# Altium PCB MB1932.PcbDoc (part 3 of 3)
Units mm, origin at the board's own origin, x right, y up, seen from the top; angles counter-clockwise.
Board outline 70 x 82.5 mm, 2 copper layers (Top Layer, Bottom Layer), stack 1.543 mm thick; 185 components, 150 nets, 679 pads, 649 vias.
Unrouted connection lines stored in the file: 108.
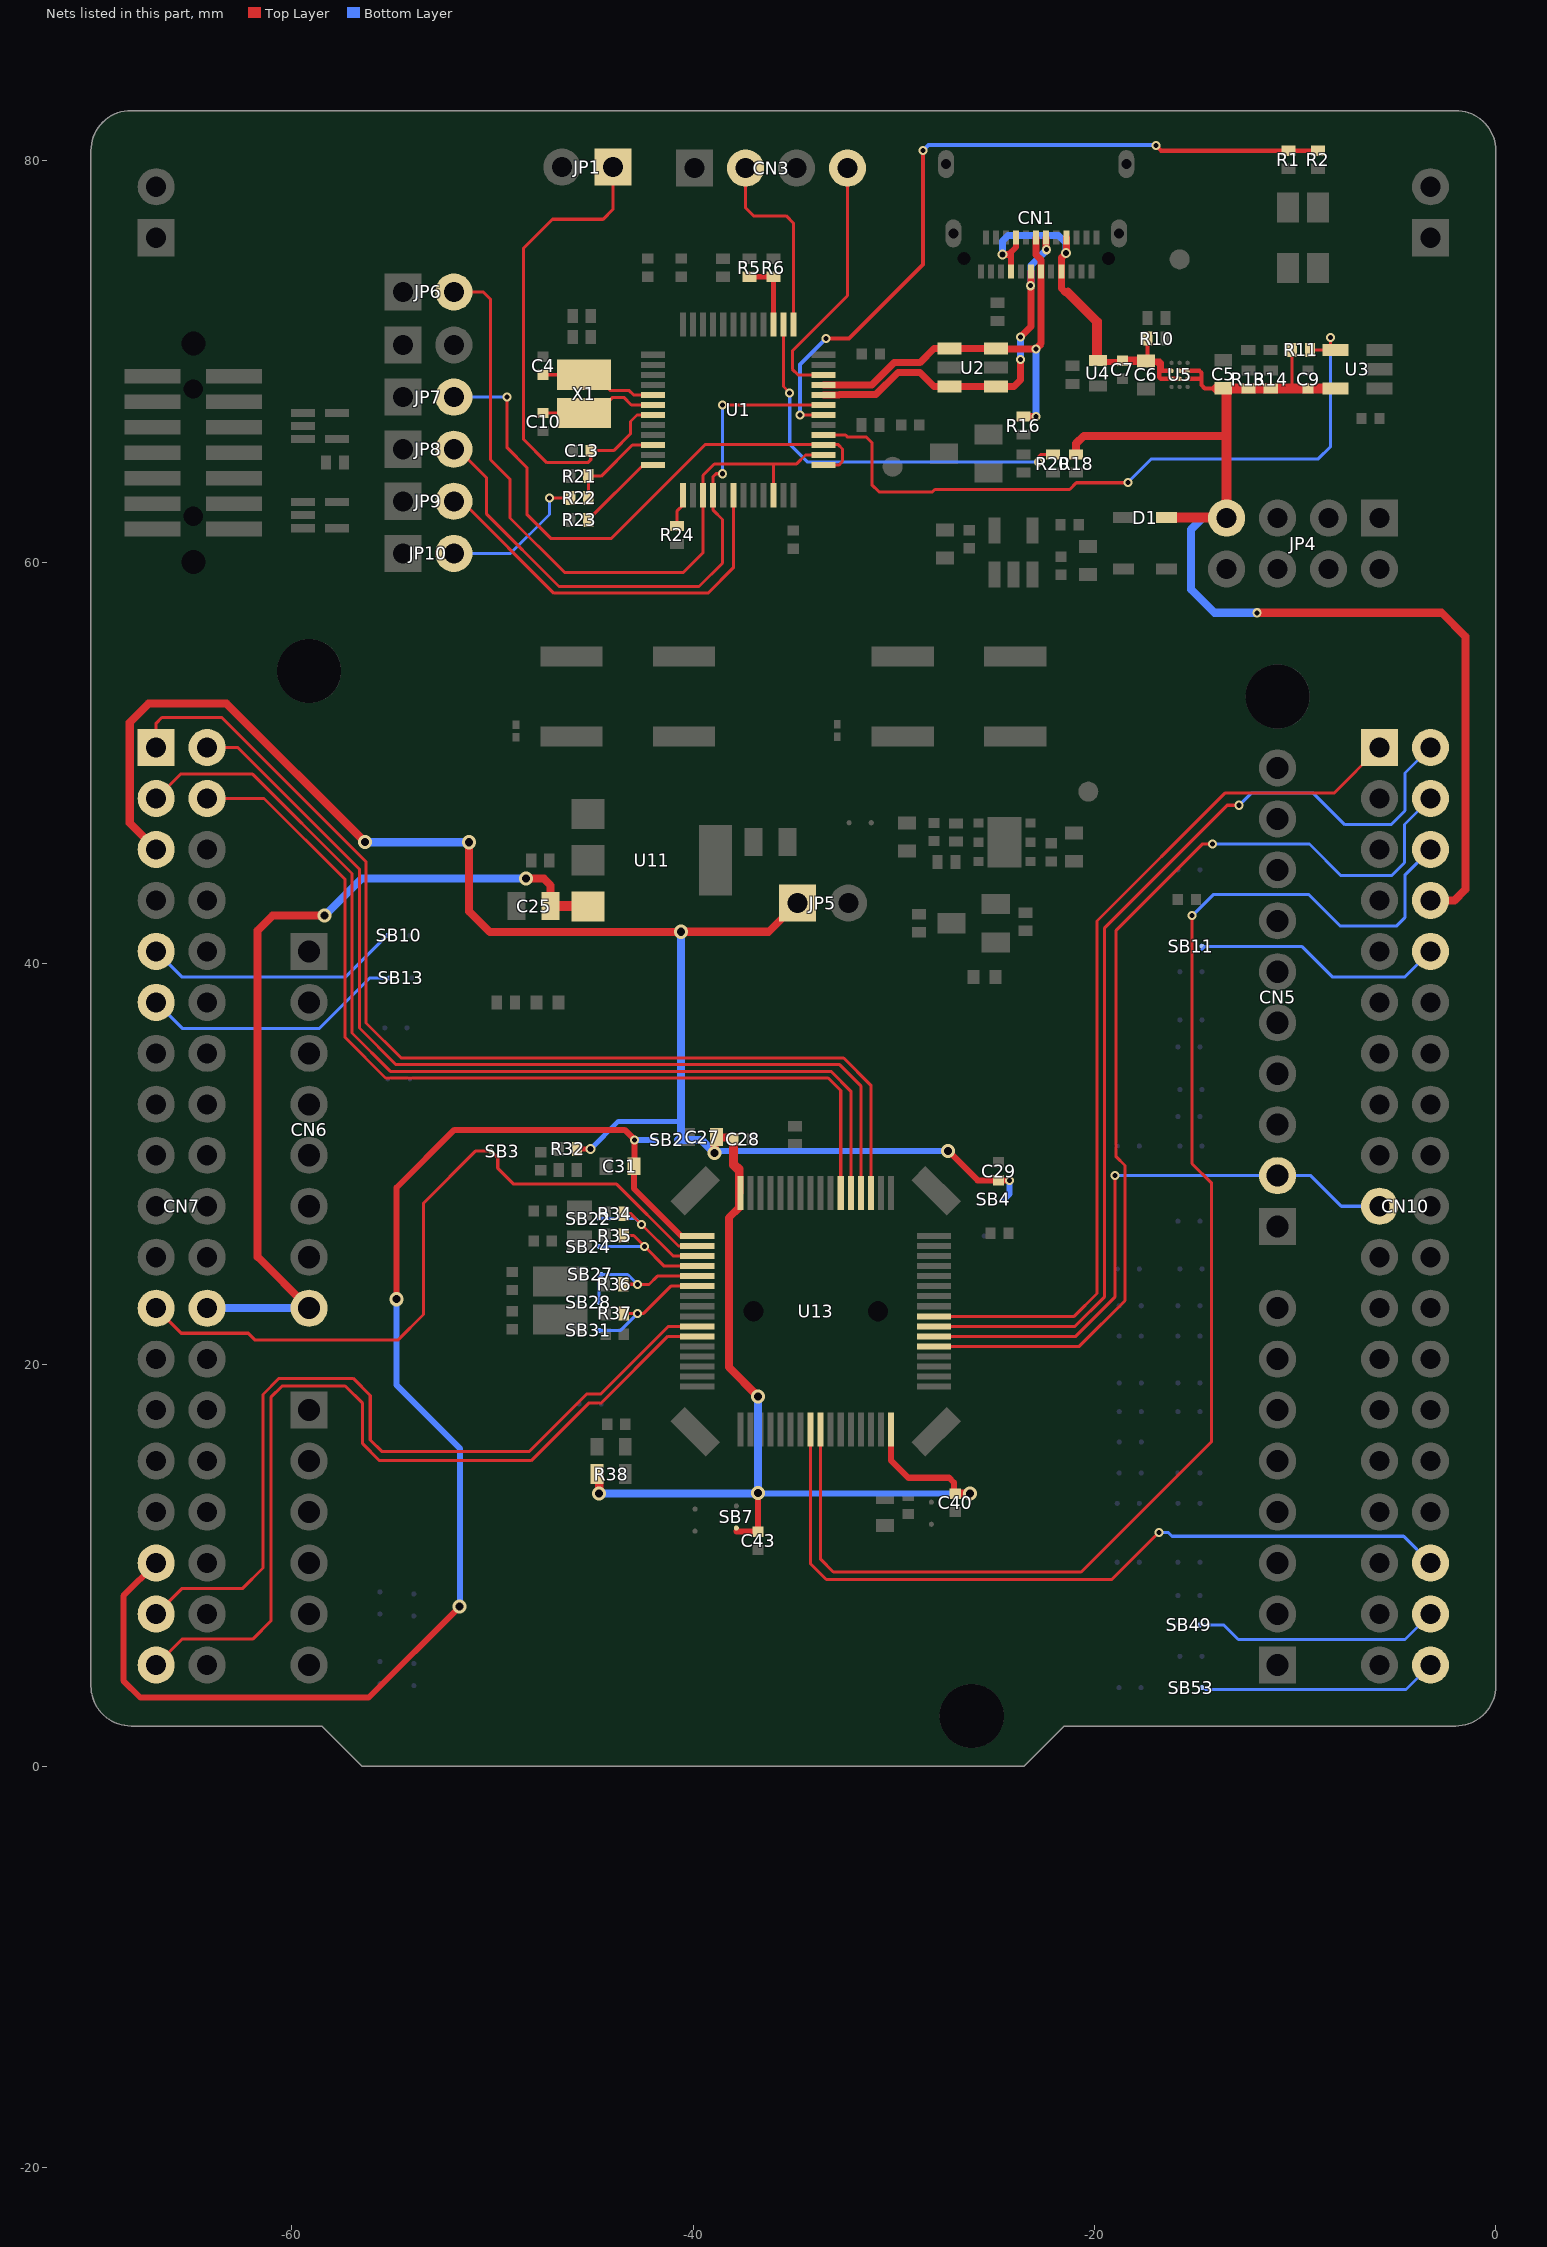
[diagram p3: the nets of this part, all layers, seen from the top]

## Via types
v1: diameter 0.45, hole 0.25, Top Layer to Bottom Layer, tented both sides, 618 vias
v2: diameter 0.7, hole 0.4, Top Layer to Bottom Layer, tented both sides, 28 vias
v3: diameter 0.5, hole 0.3, Top Layer to Bottom Layer, tented both sides, 3 vias

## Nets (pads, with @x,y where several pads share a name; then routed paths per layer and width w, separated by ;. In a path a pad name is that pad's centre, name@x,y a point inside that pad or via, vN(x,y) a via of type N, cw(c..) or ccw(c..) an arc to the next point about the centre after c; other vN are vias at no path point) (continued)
PC2: CN7.35 U13.10 | length 42.3
  Top Layer w0.152: CN7.35@-66.75,7.58 -65.483,8.847 -62.457,8.847 -61.426,9.879 -61.426,18.525 -60.626,19.325 -56.936,19.325 -56.082,18.472 -56.082,16.254 -55.513,15.685 -48.144,15.685 -45.279,18.55 -44.585,18.55 -41.218,21.918 U13.10@-39.788,21.918
PC3: CN7.37 U13.11 | length 44.5
  Top Layer w0.152: CN7.37@-66.75,5.04 -65.462,6.328 -61.942,6.328 -61.035,7.235 -61.035,18.377 -60.468,18.944 -57.33,18.944 -56.463,18.078 -56.463,16.069 -55.617,15.223 -48.067,15.223 -45.201,18.088 -44.58,18.088 -41.251,21.418 U13.11@-39.788,21.418
PC4: CN10.34 U13.24 | length 39.5
  Top Layer w0.152: U13.24@-34.138,16.768 -34.138,10.077 -33.358,9.297 -19.135,9.297 v1(-16.781,11.652)
  Bottom Layer w0.152: v1@-16.788,11.654 -16.331,11.654 -16.133,11.456 -10.371,11.456 -4.586,11.456 CN10.34@-3.25,10.12
PC5: CN10.6 U13.25 | length 71.3
  Top Layer w0.152: U13.25@-33.638,16.768 -33.638,10.307 -33.009,9.678 -20.659,9.678 -14.158,16.179 -14.158,29.052 -15.131,30.025 -15.131,42.374 v1(-15.127,42.378)
  Bottom Layer w0.152: v1(-15.127,42.378) -14.078,43.427 -9.308,43.427 -7.738,41.857 -4.957,41.857 -4.533,42.281 -4.533,44.397 CN10.6@-3.25,45.68
PC6: CN10.4 U13.37 | length 49.9
  Top Layer w0.152: U13.37@-27.988,20.918 -20.753,20.918 -18.473,23.197 -18.473,29.928 -18.912,30.366 -18.912,41.652 -14.606,45.957 v1(-14.116,45.957)
  Bottom Layer w0.152: v1@-14.116,45.949 -9.285,45.949 -7.708,44.372 -5.193,44.372 -4.543,45.022 -4.543,46.927 CN10.4@-3.25,48.22
PC7: CN5.2 CN10.19 U13.38 | length 29.7
  Top Layer w0.152: U13.38@-27.988,21.418 -20.929,21.418 -18.978,23.368 v1(-18.978,29.439)
  Bottom Layer w0.152: v1(-18.978,29.439) -18.978,29.424 CN5.2@-10.87,29.424 -9.219,29.424 -7.695,27.9 CN10.19@-5.79,27.9
PC8: CN10.2 U13.39 | length 49.9
  Top Layer w0.152: U13.39@-27.988,21.918 -20.967,21.918 -19.49,23.395 -19.49,41.772 -13.38,47.882 v1(-12.785,47.882)
  Bottom Layer w0.152: v1(-12.785,47.882) -12.183,48.484 -9.09,48.484 -7.517,46.912 -5.219,46.912 -4.52,47.61 -4.52,49.49 CN10.2@-3.25,50.76
PC9: CN10.1 U13.40 | length 44.8
  Top Layer w0.152: U13.40@-27.988,22.418 -21.006,22.418 -19.87,23.553 -19.87,42.113 -13.496,48.487 -8.063,48.487 CN10.1@-5.79,50.76
PC10: CN7.1 U13.51 | length 54.6
  Top Layer w0.152: CN7.1@-66.75,50.76 -66.75,51.967 -66.467,52.25 -63.475,52.25 -56.293,45.067 -56.293,37.033 -54.545,35.285 -32.49,35.285 -31.138,33.933 U13.51@-31.138,28.568
PC11: CN7.2 U13.52 | length 49.5
  Top Layer w0.152: CN7.2@-64.21,50.76 -62.686,50.76 -56.622,44.696 -56.622,36.782 -54.795,34.955 -32.695,34.955 -31.638,33.898 U13.52@-31.638,28.568
PC12: CN7.3 U13.53 | length 51.4
  Top Layer w0.152: CN7.3@-66.75,48.22 -65.541,49.429 -61.939,49.429 -56.988,44.477 -56.988,36.53 -55.083,34.625 -33.128,34.625 -32.138,33.635 U13.53@-32.138,28.568
PC13: CN7.23 SB3.2 U13.2 | length 37
  Top Layer w0.152: CN7.23@-66.75,22.82 -65.503,21.573 -62.158,21.573 -61.814,21.229 -54.709,21.229 -53.43,22.508 -53.43,28.057 -50.844,30.642 SB3.2@-50.057,30.642 -49.73,30.315 -49.73,29.798 -48.934,29.002 -43.804,29.002 -40.72,25.918 U13.2@-39.788,25.918
PC14: R34.2 SB22.1 U13.3 | length 6.8
  Top Layer w0.152: R34.2@-43.448,27.527 -43.098,27.527 v1(-42.565,26.993) -40.989,25.418 U13.3@-39.788,25.418
  Bottom Layer w0.152: SB22.1@-44.676,27.283 -42.855,27.283 v1(-42.565,26.993)
PC15: R35.2 SB24.1 U13.4 | length 6.6
  Top Layer w0.152: R35.2@-43.448,26.441 -42.958,26.441 v1(-42.42,25.902) -41.435,24.918 U13.4@-39.788,24.918
  Bottom Layer w0.152: SB24.1@-44.676,25.891 -42.431,25.891 v1(-42.42,25.902)
PD2: CN7.4 U13.54 | length 47.3
  Top Layer w0.152: CN7.4@-64.21,48.22 -61.375,48.22 -57.335,44.18 -57.335,36.307 -55.323,34.296 -33.268,34.296 -32.638,33.665 U13.54@-32.638,28.568
PD8: CN10.10 SB11.2 | length 12.6
  Bottom Layer w0.152: -14.64,40.691 -14.477,40.854 -9.674,40.854 -8.15,39.33 -4.52,39.33 CN10.10@-3.25,40.6
PF0: R36.2 SB27.2 SB28.1 U13.5 | length 7.2
  Top Layer w0.152: R36.2@-43.48,24.013 -42.77,24.013 v1(-42.757,24) -42.193,24 -41.776,24.418 U13.5@-39.788,24.418
  Bottom Layer w0.152: SB28.1@-44.676,23.108 -44.676,24.4 ; SB27.2@-44.576,24.5 -43.257,24.5 v1(-42.757,24)
PF1: R37.2 SB31.1 U13.6 | length 6.5
  Top Layer w0.152: R37.2@-43.448,22.565 v1(-42.757,22.565) -42.46,22.565 -41.107,23.918 U13.6@-39.788,23.918
  Bottom Layer w0.152: SB31.1@-44.676,21.717 -43.605,21.717 v1(-42.757,22.565)
PF4: CN10.38 SB53.2 | length 11.7
  Bottom Layer w0.152: -14.451,3.821 -4.469,3.821 CN10.38@-3.25,5.04
PF5: CN10.36 SB49.1 | length 12.3
  Bottom Layer w0.152: SB49.1@-14.74,7.036 -13.552,7.036 -12.826,6.31 -4.52,6.31 CN10.36@-3.25,7.58
PF6: CN7.9 SB10.2 | length 12.9
  Bottom Layer w0.152: CN7.9@-66.75,40.6 -65.483,39.333 -57.302,39.333 SB10.2@-55.21,41.425
PF7: CN7.11 SB13.1 | length 13.2
  Bottom Layer w0.152: CN7.11@-66.75,38.06 -65.457,36.767 -58.608,36.767 -56.096,39.279 SB13.1@-55.109,39.279
STLK_LED: R1.2 R2.1 U1.30 | length 37.5
  Top Layer w0.152: v1(-34.66,67.331) -34.659,67.33 U1.30@-33.493,67.33
  Top Layer w0.203: v1(-33.375,71.132) -32.235,71.132 -28.543,74.825 v1(-28.543,80.496) ; v1(-16.937,80.763) -16.671,80.496 R2.1@-8.863,80.496
  Bottom Layer w0.203: v1(-34.66,67.331) -34.66,69.848 v1(-33.375,71.132) ; v1(-28.543,80.496) -28.257,80.783 -16.957,80.783 v1(-16.937,80.763)
STLK_NRST: C13.2 JP1.1 U1.7 | length 25.4
  Top Layer w0.152: JP1.1@-43.993,79.68 -43.993,77.566 -44.477,77.082 -47.004,77.082 -48.45,75.636 -48.45,66.116 -47.285,64.951 -45.239,64.951 -45.096,65.094 C13.2@-45.096,65.548 -43.952,65.548 -43.114,66.386 -43.114,67.006 -42.79,67.33 U1.7@-41.993,67.33
STLK_OSC_IN: C4.2 U1.5 X1.2 | length 6.1
  Top Layer w0.152: C4.2@-47.473,69.332 X1.2@-45.439,69.332 ; X1.2@-46.351,69.332 -45.662,69.332 X1.2@-45.23,68.901 ; X1.2@-44.474,68.901 -44.111,68.538 -43.175,68.538 -42.967,68.33 U1.5@-41.993,68.33
STLK_OSC_OUT: C10.1 U1.6 X1.1 | length 6
  Top Layer w0.152: C10.1@-47.473,67.432 X1.1@-45.439,67.432 -44.778,67.432 -44.003,68.208 -43.448,68.208 -43.07,67.83 U1.6@-41.993,67.83
STLK_SWCLK: CN3.2 U1.37 | length 9.7
  Top Layer w0.152: CN3.2@-37.38,79.63 -37.38,77.651 -36.981,77.252 -35.356,77.252 -34.993,76.89 U1.37@-34.993,71.83
STLK_SWDIO: CN3.4 U1.34 | length 12.9
  Top Layer w0.152: U1.34@-33.493,69.33 -34.769,69.33 -35.051,69.612 -35.051,70.521 -32.3,73.272 CN3.4@-32.3,79.562 ; CN3.4@-32.3,79.63 CN3.4@-32.3,79.562 ; CN3.4@-32.233,79.629 CN3.4@-32.3,79.562
STLK_USB_N: CN1.A7 CN1.B7 U1.32 U2.3 U2.4 | length 19.2
  Top Layer w0.35: U1.32@-33.493,68.33 -32.718,68.33 -32.707,68.341 -30.893,68.341 -29.78,69.455 -28.697,69.455 -27.985,68.743 U2.3@-27.21,68.743 U2.4@-24.91,68.743 -24.004,68.743 -23.673,69.075 v1(-23.673,70.098) ; v1(-23.673,71.212) -23.15,71.735 v1@-23.15,73.745 ; v1(-23.179,73.769) -23.174,73.769 v1@-23.15,73.745 ; CN1.A7@-23.15,74.471 v1@-23.15,73.745 ; CN1.B7@-22.4,76.171 -22.4,75.55 -22.375,75.525 v1(-22.375,75.563)
  Bottom Layer w0.35: v1(-23.673,70.098) v1(-23.673,71.212) ; v1(-23.179,73.769) -23.156,73.769 -23.152,73.772 -23.152,74.785 v1(-22.375,75.563)
STLK_USB_P: CN1.A6 CN1.B6 R16.1 U1.33 U2.1 U2.6 | length 21.1
  Top Layer w0.35: U1.33@-33.493,68.83 -32.718,68.83 -32.707,68.818 -31.091,68.818 -29.978,69.932 -28.697,69.932 -27.985,70.643 U2.1@-27.21,70.643 U2.6@-24.91,70.643 -24.909,70.645 -24.889,70.625 v1(-22.905,70.625) -22.65,70.88 CN1.A6@-22.65,74.471 -22.65,75.045 -22.902,75.297 -22.902,75.781 -22.9,75.783 CN1.B6@-22.9,76.171 ; R16.1@-23.54,67.25 v1@-22.913,67.25
  Bottom Layer w0.35: v1(-22.91,67.252) v1@-22.91,70.625
STLK_VCP_RX: R24.1 U1.13 | length 1.7
  Top Layer w0.152: R24.1@-40.79,61.8 -40.79,62.55 -40.493,62.847 U1.13@-40.493,63.33
STLK_VCP_TX: R23.1 U1.12 | length 4.5
  Top Layer w0.152: R23.1@-45.218,61.887 -45.218,62.02 R23.1@-45.176,62.061 ; R23.1@-45.218,62.102 -42.49,64.83 U1.12@-41.993,64.83
T_NRST: JP9.2 U1.18 | length 19.8
  Top Layer w0.152: JP9.2@-51.714,63.028 -51.51,63.028 -46.935,58.453 -39.252,58.453 -37.993,59.712 U1.18@-37.993,63.33
T_PWR_EN: R11.1 U1.28 U3.4 | length 36.2
  Top Layer w0.152: U1.28@-33.493,66.33 -32.392,66.33 -32.289,66.226 -31.359,66.226 -31.087,65.955 -31.087,63.852 -30.724,63.489 -28.079,63.489 -27.948,63.62 -21.233,63.62 -20.901,63.951 -18.344,63.951 v1(-18.333,63.963) ; R11.1@-9.261,70.571 -8.006,70.571 U3.4@-7.991,70.556 U3.4@-7.681,70.556 ; U3.4@-8.225,70.594 v1(-8.225,71.191)
  Bottom Layer w0.152: v1(-18.333,63.963) -17.152,65.144 -8.841,65.144 -8.225,65.761 v1(-8.225,71.191)
T_PWR_EXT: R5.1 R6.1 U1.39 | length 3.6
  Top Layer w0.152: R6.1@-35.996,74.216 R6.1@-35.993,74.214
  Top Layer w0.254: R5.1@-37.186,74.216 R6.1@-35.996,74.216 ; U1.39@-35.993,71.83 R6.1@-35.993,74.214
T_SWCLK: JP6.2 U1.15 U1.22 U1.26 | length 36.1
  Top Layer w0.152: JP6.2@-51.715,73.458 -50.448,73.458 -50.089,73.099 -50.089,65.103 -49.115,64.129 -49.115,62.198 -46.402,59.485 -40.478,59.485 -39.506,60.456 -39.506,64.319 -38.935,64.89 -35.993,64.89 U1.22@-35.993,63.33 ; -35.989,64.891 -34.834,64.891 -34.395,65.33 U1.26@-33.493,65.33
T_SWDIO: JP7.2 U1.25 U1.27 | length 28.6
  Top Layer w0.152: v1(-49.26,68.217) -49.26,65.693 -48.28,64.712 -48.28,62.378 -47.068,61.165 -44.083,61.165 -39.399,65.849 -32.764,65.849 -32.546,65.632 -32.546,65.027 -32.744,64.83 U1.25@-33.493,64.83
  Bottom Layer w0.152: JP7.2@-51.714,68.217 v1(-49.26,68.217)
T_SWO: JP8.2 U1.16 U1.31 | length 31.1
  Top Layer w0.152: JP8.2@-51.714,65.621 -50.283,64.189 -50.283,62.384 -46.681,58.783 -39.699,58.783 -38.535,59.946 -38.535,62.125 -38.993,62.583 U1.16@-38.993,63.33 -38.993,64.264 -38.857,64.4 v1(-38.53,64.4) ; v1@-38.53,67.83 U1.31@-33.493,67.83
  Bottom Layer w0.152: v1@-38.53,64.397 v1(-38.53,64.4) v1@-38.53,67.835
  other v1: -38.527,67.835
T_VCC: JP10.2 R22.2 | length 7.2
  Top Layer w0.152: v1(-47.155,63.202) R22.2@-46.117,63.202
  Bottom Layer w0.152: JP10.2@-51.713,60.432 -49.093,60.432 -47.155,62.37 v1(-47.155,63.202)
T_VCC_AIN: R21.1 R22.1 U1.10 | length 5
  Top Layer w0.152: R22.1@-45.218,63.099 R21.1@-45.218,64.278 -44.576,64.278 -43.024,65.83 U1.10@-41.993,65.83
USB_RENUMn: R20.2 U1.38 | length 19.9
  Top Layer w0.152: U1.38@-35.493,71.83 -35.493,68.746 v1(-35.18,68.433) ; v1(-22.78,64.992) -22.78,65.255 -22.675,65.36 R20.2@-22.064,65.36
  Bottom Layer w0.152: v1(-35.18,68.433) -35.18,65.865 -34.307,64.992 v1(-22.78,64.992)
VBAT/VLCD/VDD: C31.1 CN7.33 SB2.2 U13.1 | length 68.5
  Top Layer w0.3: CN7.33@-66.75,10.12 -68.383,8.487 -68.383,4.26 -67.543,3.419 -56.158,3.419 v2(-51.627,7.951) ; v2(-54.766,23.267) -54.766,28.833 -51.893,31.707 -43.407,31.707 v1(-42.908,31.207) C31.1@-42.908,29.925 ; C31.1@-42.94,29.893 -42.94,28.775 -40.583,26.418 U13.1@-39.788,26.418
  Bottom Layer w0.3: v2(-54.766,23.267) -54.766,18.987 -51.619,15.84 v2@-51.619,7.951 ; v1(-42.908,31.207) SB2.2@-41.857,31.207
VBUS: C6.1 C7.1 CN1.A4 CN1.A9 CN1.B4 CN1.B9 R10.2 U4.1 U5.B3 U5.C2 U5.C3 | length 27.6
  Top Layer w0.215: C6.1@-17.423,69.914 -16.873,69.914 ; R10.2@-17.352,71.129 -17.352,70.105 -17.368,70.089 C6.1@-17.432,70.025 -16.882,70.025 ; -16.88,69.913 -16.772,69.805 ; -16.769,69.803 -16.772,69.805 ; U5.C2@-16.153,69.526 -16.632,69.526 -16.632,69.924 -16.733,70.025 -16.882,70.025 ; U5.B3@-15.753,69.126 -16.693,69.126 -16.772,69.205 -16.772,69.805 ; -16.882,70.025 -16.772,69.914 -16.772,69.805
  Top Layer w0.3: -24.278,75.323 -24.15,75.45 ; CN1.A9@-24.15,74.471 -24.15,75.45 ; CN1.B4@-23.9,76.171 -23.9,75.7 -24.15,75.45 ; -21.425,73.41 -19.98,71.965 -19.98,70.188 U4.1@-19.825,70.033 ; v3(-21.42,75.393) v3@-21.4,75.413 ; -21.303,73.532 -19.783,72.011 U4.1@-19.783,70.037 ; U4.1@-20.127,70.025 U4.1@-19.831,70.025 ; U4.1@-19.832,70.026 U4.1@-19.831,70.025 ; U4.1@-19.812,70.005 U4.1@-19.831,70.025 ; U4.1@-19.801,70.056 U4.1@-19.783,70.037 ; C7.1@-18.601,70.089 C6.1@-17.368,70.089 ; C6.1@-17.432,69.98 -19.783,69.98 U4.1@-19.783,70.025 ; U4.1@-19.831,70.025 U4.1@-19.783,70.025 ; U4.1@-19.783,70.025 U4.1@-19.783,70.037 ; U4.1@-19.783,70.025 -19.771,70.025 U4.1@-19.783,70.037
  Top Layer w0.35: v3(-24.57,75.323) -24.278,75.323 ; -21.425,73.41 -21.647,73.632 -21.647,75.165 v3(-21.42,75.393) ; v3@-21.4,75.413 CN1.B9@-21.4,76.171
  Bottom Layer w0.35: v3(-24.57,75.323) -24.57,76.001 -24.298,76.272 -21.782,76.272 -21.42,75.91 v3(-21.42,75.393)
VBUS_STLK: C5.2 C9.2 CN10.8 D1.1 JP4.7 R11.2 R13.2 R14.2 R18.2 U3.5 U5.A2 U5.A3 U5.B2 | length 61.9
  Top Layer w0.152: -10.161,68.67 R11.2@-10.161,70.571
  Top Layer w0.215: U5.B2@-15.753,69.526 -14.762,69.526 -14.664,69.428 -14.664,68.819 -14.495,68.651 -14.054,68.651 ; U5.A3@-15.353,69.126 -14.666,69.126
  Top Layer w0.4: R18.2@-20.911,65.36 -20.911,65.902 -20.521,66.292 -13.568,66.292 ; v1(-11.904,57.473) -2.694,57.473 -1.518,56.297 -1.518,43.676 -2.054,43.14 CN10.8@-3.25,43.14
  Top Layer w0.5: D1.1@-16.404,62.215 JP4.7@-13.902,62.215 ; C5.2@-13.902,68.652 C9.2@-9.38,68.652 ; JP4.7@-13.41,62.19 C5.2@-13.41,68.493 ; C9.2@-9.355,68.648 U3.5@-7.999,68.648
  Bottom Layer w0.4: JP4.7@-13.41,62.19 -14.614,62.19 -15.186,61.618 -15.186,58.644 -14.015,57.473 v1(-11.904,57.473)
VDD: C27.2 C28.2 C29.2 C40.2 C43.2 CN7.5 JP5.1 R32.2 R38.1 SB2.1 SB4.1 SB7.1 U13.32 U13.64 | length 135
  Top Layer w0.25: R32.2@-45.785,30.76 v3@-45.105,30.76
  Top Layer w0.3: C28.2@-38.048,31.322 -38.048,29.923 -37.713,29.588 -37.638,29.513 ; C28.2@-37.997,31.318 -37.906,31.228 -37.906,30.054 -37.638,29.786 -37.638,29.513 ; -37.84,11.71 -37.832,11.702 C43.2@-36.76,11.702 ; U13.64@-37.638,28.568 -37.638,29.513 ; C43.2@-36.761,11.703 v2(-36.761,13.604) ; U13.32@-30.138,16.768 -30.138,15.237 -29.272,14.372 -27.238,14.372 -26.994,14.128 -26.994,13.625 C40.2@-26.938,13.569 ; v2(-27.287,30.662) -25.817,29.192 C29.2@-24.777,29.192 v1@-24.238,29.192
  Top Layer w0.4: CN7.5@-66.75,45.68 -68.066,46.996 -68.066,52.007 -67.131,52.942 -63.242,52.942 v2(-56.35,46.05) ; v2(-51.16,46.038) -51.16,42.597 -50.126,41.563 -40.623,41.563 v2(-40.608,41.578) -36.228,41.578 JP5.1@-34.798,43.008 ; v2@-44.672,13.597 R38.1@-44.672,14.548 ; v2(-38.925,30.558) -38.925,31.22 -38.822,31.323 C28.2@-38.001,31.323 ; -37.713,29.625 -37.713,29.588 -37.713,27.829 -38.216,27.326 -38.216,19.885 v2(-36.759,18.428) ; C43.2@-36.761,11.703 -36.76,11.702 C43.2@-36.76,11.683 ; C40.2@-26.938,13.569 -26.91,13.597 v2(-26.199,13.597)
  Bottom Layer w0.152: -36.76,14.007 -36.754,14.013
  Bottom Layer w0.25: v3(-45.097,30.752) -43.719,32.13 -40.601,32.13
  Bottom Layer w0.3: v2(-38.925,30.558) -38.82,30.662 v2(-27.287,30.662) ; v2@-36.76,13.597 v2(-26.199,13.597) ; SB4.1@-24.487,28.255 -24.22,28.523 v1(-24.22,29.175)
  Bottom Layer w0.4: v2(-56.35,46.05) -56.338,46.038 v2(-51.16,46.038) ; SB2.1@-40.758,31.207 -40.601,31.207 ; v2@-40.601,41.578 -40.601,32.13 -40.601,31.207 ; v2(-38.925,30.558) -39.575,31.207 -40.601,31.207 ; v2(-36.761,13.604) -36.761,13.598 v2@-36.76,13.597 ; v2@-36.76,18.428 -36.76,14.007 v2@-36.76,13.597 ; v2(-44.675,13.597) v2@-36.76,13.597 ; v2(-44.675,13.597) -44.675,13.499 -44.773,13.597 v2(-44.675,13.597)
VIN: C25.2 CN6.8 CN7.24 U11.3 | length 43.8
  Top Layer w0.4: CN6.8@-59.13,22.82 -61.69,25.38 -61.69,41.636 -60.949,42.378 v2(-58.358,42.378) ; v2(-48.314,44.221) -47.425,44.221 -47.098,43.894 C25.2@-47.098,42.853
  Top Layer w0.5: C25.2@-47.272,42.853 C25.2@-47.098,42.853 -45.246,42.853 U11.3@-45.237,42.844
  Bottom Layer w0.4: CN7.24@-64.21,22.82 CN6.8@-59.13,22.82 ; v2(-58.358,42.378) -56.515,44.221 v2(-48.314,44.221)
pads on no net: CN1.0 CN1.A2 CN1.A3 CN1.A8 CN1.A10 CN1.A11 CN1.B2 CN1.B3 CN1.B8 CN1.B10 CN1.B11 CN4.0 CN4.1 CN4.2 CN4.10 CN7.10 CN7.26 U1.4 U1.11 U1.14 U1.17 U1.19 U1.21 U1.40 U1.41 U1.42 U1.43 U1.45 U1.46 U2.5 U13.0

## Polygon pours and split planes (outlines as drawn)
GND on Top Layer "Top Layer-GND" (solid, remove dead copper, pour order 0): -69.936,3.998 ccw(c-68,3.998) -68.002,2.062 ccw(c-68,3.998) -68,2.062 -58.5,2.062 cw(c-58.5,1.998) -58.455,2.044 -56.473,0.062 -23.526,0.062 -21.594,1.995 cw(c-21.53,1.998) -21.53,2.062 -21.502,2.062 cw(c-21.5,1.998) -21.497,2.062 -2,2.062 ccw(c-2,3.998) -0.064,3.998 cw(c0,3.998) -0.064,3.999 -0.064,80.498 ccw(c-2,80.498) -1.999,82.435 cw(c-2,82.498) -2,82.435 -68,82.435 cw(c-68,82.498) -68,82.435 ccw(c-68,80.498) -69.936,80.498 cw(c-70,80.498) -69.936,80.498 -69.936,57.998 cw(c-70,57.998) -69.937,57.986 cw(c-70,57.974) -69.936,57.974
GND on Bottom Layer "Bottom Layer-GND" (solid, remove dead copper, pour order 2): -69.936,3.998 ccw(c-68,3.998) -68.002,2.062 ccw(c-68,3.998) -68,2.062 -58.5,2.062 cw(c-58.5,1.998) -58.455,2.044 -56.473,0.062 -23.526,0.062 -21.594,1.995 cw(c-21.53,1.998) -21.53,2.062 -21.502,2.062 cw(c-21.5,1.998) -21.497,2.062 -2,2.062 ccw(c-2,3.998) -0.064,3.998 cw(c0,3.998) -0.064,3.999 -0.064,80.498 ccw(c-2,80.498) -1.999,82.435 cw(c-2,82.498) -2,82.435 -68,82.435 cw(c-68,82.498) -68,82.435 ccw(c-68,80.498) -69.936,80.498 cw(c-70,80.498) -69.936,80.498 -69.936,57.998 cw(c-70,57.998) -69.937,57.986 cw(c-70,57.974) -69.936,57.974

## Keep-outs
Keep-Out Layer:
  lines w0.127: -70,3.998 ccw(c-68,3.998) -68,1.998 ; -70,80.498 cw(c-68,80.498) -68,82.498 ; -2,1.998 ccw(c-2,3.998) 0,3.998 ; -2,82.498 cw(c-2,80.498) 0,80.498
  lines w0.152: -70,3.998 -70,57.974 ; -70,57.998 -70,80.498 ; -68,1.998 -58.63,1.998 -58.5,1.998 -56.5,-0.002 -23.5,-0.002 -21.5,1.998 ; -68,82.498 -2,82.498 ; -21.53,1.998 -2,1.998 ; 0,3.998 0,56.998 0,80.498

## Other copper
Top Layer:
  pour cut-out: -42.535,38.403 -42.535,37.918 -42.367,37.751 -41.628,37.751 -41.628,38.188 -41.508,38.308 -41.708,38.508 -42.043,38.508 -42.063,38.528
  region net GND: -46.668,60.237 -46.668,60.812 -46.74,60.885 -46.747,60.878 -47.142,60.878 -47.142,60.69 -47.15,60.682 -46.737,60.27 -46.71,60.27
  region net GND: -32.671,69.902 -32.671,69.268 -32.525,69.123 -31.23,69.123 -29.777,70.575 -29.777,71.038 -30.938,71.038 -30.937,70.233 -31.268,69.902
  region net NetCN1_A5: -22.201,73.449 -20.897,72.145 -20.897,69.675 -21.188,69.675 -21.308,69.795 -21.307,71.895 -22.297,72.885 -22.297,73.448
  region net VBUS: -21.798,74.232 -19.637,72.072 -19.637,70.267 -19.717,70.188 -20.083,70.188 -20.154,70.259 -20.154,71.884 -21.798,73.528
  region net VBUS: -17.818,70.22 -19.638,70.22 -19.801,70.056 -19.573,69.828 -17.51,69.828 -17.423,69.914 -17.423,70.213 -17.437,70.227
  pour cut-out: -54.289,20.467 -54.289,19.647 -54.464,19.472 -54.657,19.665 -54.854,19.665 -54.854,20.119 -54.825,20.148
  pour cut-out: -19.973,40.859 -19.981,40.867 -20.76,40.867 -20.76,40.926 -20.433,41.253 -20.38,41.199 -20.116,41.199
  pour cut-out: -58.401,44.702 -58.63,44.473 -58.63,44.303 -58.388,44.062 -58.033,44.062 -57.84,44.255 -57.84,44.468 -58.122,44.75 -58.279,44.75
  pour cut-out: -62.94,28.852 -60.335,28.852 -60.4,28.917 -60.4,30.748 -62.809,30.748 -62.899,30.658
  pour cut-out: -44.407,44.164 -44.383,44.188 -44.147,44.188 -44.12,44.161 -44.12,43.717
  pour cut-out: -48.525,25.176 -48.501,25.2 -48.265,25.2 -48.238,25.173 -48.238,24.729
  region net GND: -16.97,68.824 -17.107,68.687 -17.107,68.3 -17.034,68.227 -15.294,68.227 -15.162,68.359 -15.162,68.751 -15.239,68.828
  pour cut-out: -50.832,9.262 -50.832,6.745 -51.352,6.224 -51.802,6.674 -53.026,6.674 -53.026,8.31 -52.473,8.863
  region net GND: -24.023,59.373 -24.322,59.074 -24.322,58.113 -24.266,58.057 -23.743,58.057 -23.621,58.179 -23.621,58.417 -23.73,58.527 -23.73,58.881 -23.823,58.973
  region net 3V3_STLK: -40.471,74.319 -40.748,74.042 -40.748,72.607 -40.573,72.431 -40.427,72.434 -40.232,72.629 -40.232,74.081
  region net 3V3_STLK: -35.059,62.69 -35.254,62.495 -35.254,61.702 -35.188,61.636 -34.794,61.636 -34.716,61.715 -34.716,62.469 -34.937,62.69
  region net 3V3_STLK: -32.815,70.479 -32.739,70.554 -31.53,70.554 -31.471,70.495 -31.471,70.281 -31.576,70.176 -32.757,70.176 -32.812,70.231
  region net VBUS: -16.518,69.632 -16.518,69.205 -16.597,69.126 -16.772,69.301 -16.772,69.914
  region net VBUS_STLK: -14.943,69.555 -14.943,68.661 -14.714,68.433 -13.703,68.433 -13.571,68.565 -13.571,68.793 -13.688,68.91 -14.298,68.91 -14.358,68.97 -14.358,69.501 -14.488,69.632 -14.892,69.632
  text ".Layer_Name" at -73.879,-14.121 h3
  text ".GTL" at -32.184,-14.121 h3
Bottom Layer:
  pour cut-out: -25.137,27.105 -25.137,27.445 -25.232,27.35 -25.232,27.213 -25.215,27.195
  region net GND: -25.137,26.922 -25.137,27.105 -24.952,26.92 -24.945,26.92 -24.923,26.898 -24.923,26.84
  region net GND: -25.137,25.923 -25.137,25.627 -25.057,25.548 -24.823,25.782 -24.823,25.843 -24.933,25.953 -24.963,25.923
  region net MCU.VCP_TX: -61.263,59.11 -60.999,58.847 -60.99,58.847 -61.292,58.545 -61.3,58.545 -61.3,59.073
  pour cut-out: -15.674,58.412 -14.968,58.412 -14.694,58.138 -14.694,57.546 -15.631,57.546 -15.786,57.701
  pour cut-out: -57.712,42.301 -57.712,41.261 -57.924,41.049
  pour cut-out: -56.289,11.435 -55.286,11.435 -54.854,11.003 -54.854,9.949 -54.865,9.949
  pour cut-out: -12.931,58.539 -12.931,57.833 -13.015,57.749 -13.071,57.805 -13.797,57.805 -13.797,58.496 -13.642,58.651
  pour cut-out: -18.715,6.463 -18.715,3.193 -18.598,3.076 -16.507,3.076 -16.454,3.129 -16.454,5.644 -17.656,6.846
  pour cut-out: -16.959,47.409 -16.958,4.547 -15.497,4.547 -15.497,28.678 -15.593,28.774 -15.593,47.409
  pour cut-out: -18.208,34.83 -18.208,33.892 -18.08,33.764 -18.037,33.806 -16.746,33.806 -16.746,34.606 -16.843,34.703 -16.843,34.721
  pour cut-out: -18.782,40.813 -18.782,39.875 -18.654,39.747 -18.611,39.789 -17.32,39.789 -17.32,40.589 -17.417,40.686 -17.417,40.704
  pour cut-out: -15.667,43.722 -15.667,42.785 -15.538,42.656 -15.496,42.699 -14.205,42.699 -14.205,43.499 -14.301,43.595 -14.301,43.613
  pour cut-out: -14.591,47.023 -14.591,46.085 -14.463,45.957 -14.42,45.999 -13.129,45.999 -13.129,46.799 -13.226,46.896 -13.226,46.914
  pour cut-out: -66.788,28.04 -64.197,25.449 -64.197,27.844 -64.345,27.991
  pour cut-out: -59.032,18.981 -58.753,19.261 -56.899,19.261 -56.899,18.509 -57.056,18.351
  text ".GBL" at -43.387,-14.153 h3
  text ".Layer_Name" at -2.073,-14.153 h3
Multi-Layer:
  pour cut-out: -4.62,80.07 -1.88,80.07 -1.88,74.79 -4.62,74.79
  pour cut-out: -68.12,80.07 -65.38,80.07 -65.38,74.79 -68.12,74.79
  pour cut-out: -41.23,80.93 -41.23,78.33 -30.99,78.33 -30.99,80.93
  pour cut-out: -47.803,80.95 -47.843,80.91 -47.843,78.38 -42.683,78.38 -42.683,80.98 -47.843,80.98
  pour cut-out: -50.604,59.132 -50.605,74.682 -55.765,74.682 -55.764,59.132
  pour cut-out: -36.108,44.308 -30.948,44.308 -30.948,41.708 -36.108,41.708
  pour cut-out: -14.68,63.46 -4.52,63.46 -4.52,58.38 -14.68,58.38 -14.68,63.46
  pour cut-out: -57.925,19.265 -57.926,19.264 -60.336,19.264 -60.336,3.516 -60.335,3.515 -57.925,3.515 -57.925,19.262 -57.923,19.264
  pour cut-out: -12.076,51.268 -12.075,51.267 -12.075,30.439 -9.665,30.439 -9.647,30.457 -9.647,51.252
  pour cut-out: -60.336,42.124 -60.335,42.123 -60.335,21.295 -57.925,21.295 -57.907,21.313 -57.907,42.108
  pour cut-out: -68.02,52.03 -68.02,3.77 -62.94,3.77 -62.94,52.03
  pour cut-out: -7.06,52.03 -7.06,3.77 -1.98,3.77 -1.98,52.03

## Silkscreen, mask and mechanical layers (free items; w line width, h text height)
Top Overlay:
  circle w0.127: c-30.657,39.99 r0.209
  circle w0.127: c-36.067,40.041 r0.203
  circle w0.127: c-33.273,39.99 r1.42
  lines w0.152: -57.725,33.996 -54.533,33.996 -54.533,30.694 ; -57.606,3.77 -54.533,3.77 -54.533,10.044 -54.533,11.365 ; -57.606,19.01 -54.533,19.01 -54.533,14.438 ; -57.606,21.55 -54.533,21.55 -54.533,24.598 ; -36.067,40.041 -34.695,40.041 ; -31.853,39.99 -30.657,39.99
  text "STLK_RST" at -48.389,77.161 h1.52
  text "RESERVED" at -39.751,76.708 h1.78
  text "J" at -63.248,74.792 h15.24
  text "COM" at -11.332,72.507 h1.78
  text "STLINK" at -23.992,71.87 h1.78
  text "5V SOURCE" at -11.232,63.676 h1.2
  text "MCO" at -32.144,62.278 h1.78
  text "DEBUG_IN" at -68.426,57.078 h1.78
  text "USER" at -45.29,56.75 h1.78
  text "RESET" at -29.14,56.699 h1.78
  text "VIN" at -7.806,55.676 h1.78 r90
  text "E5V" at -10.38,55.322 h1.78 r90
  text "CHG" at -12.973,54.819 h1.78 r90
  text "STLK" at -5.193,54.287 h1.78 r90
  text "L" at -56.64,52.55 h10.16
  text "SCL/D15" at -18.744,49.236 h1.78
  text "SDA/D14" at -18.744,47.204 h1.78
  text "E5V" at -62.432,45.172 h1.78
  text "AVDD" at -16.712,44.156 h1.78
  text "GND" at -62.432,42.632 h1.78
  text "GND" at -15.696,41.616 h1.78
  text "A" at -34.009,39.271 h2.54
  text "SCK/D13" at -18.998,39.076 h1.78
  text "IOREF" at -57.606,37.552 h1.78
  text "IDD" at -34.698,37.065 h1.78
  text "MISO/D12" at -19.506,36.536 h1.78
  text "NRST" at -57.606,35.012 h1.78
  text "PWM/MOSI/D11" at -23.824,33.996 h1.78
  text "3V3" at -57.606,32.472 h1.78
  text "PWM/CS/D10" at -22.046,31.456 h1.78
  text "5V" at -57.606,29.932 h1.78
  text "PWM/D9" at -18.49,28.916 h1.78
  text "GND" at -57.606,27.392 h1.78
  text "D8" at -14.172,26.376 h1.78
  text "GND" at -57.606,24.852 h1.78
  text "POWER" at -52.767,24.75 h1.78 r90
  text "VIN" at -57.606,22.312 h1.78
  text "D7" at -14.172,22.312 h1.78
  text "PWM/D6" at -18.49,19.772 h1.78
  text "A0" at -57.352,17.232 h1.78
  text "PWM/D5" at -18.49,17.232 h1.78
  text "A1" at -57.352,14.692 h1.78
  text "D4" at -14.426,14.692 h1.78
  text "A2" at -57.352,12.152 h1.78
  text "PWM/D3" at -18.744,12.152 h1.78
  text "AIN" at -53.849,11.69 h1.78 r90
  text "A3" at -57.352,9.612 h1.78
  text "D2" at -14.426,9.612 h1.78
  text "A4" at -57.352,7.072 h1.78
  text "TX/D1" at -16.966,7.072 h1.78
  text "MB1932B" at -27.623,5.107 h2.5
  text "A5" at -57.352,4.532 h1.78
  text "RX/D0" at -16.966,4.532 h1.78
  text ".Layer_Name" at -73.879,-14.121 h3
  text ".GTO" at -32.184,-14.121 h3
Bottom Overlay:
  drawing of 169 lines, arcs and shapes, not listed
  text "G" at -49.712,51.912 h10.16
  text "I" at -29.791,51.623 h10.16
  text "C" at -19.731,51.536 h10.16
  text "S" at -39.229,51.027 h10.16
  text "F" at -50.768,43.765 h10.16
  text "E" at -40.005,43.772 h10.16
  text "H" at -22.046,43.772 h10.16
  text "CN5" at -9.346,24.344 h1.78
  text "CN6" at -57.606,19.772 h1.78
  text "CN7" at -63.956,2.246 h1.78
  text "CN8" at -57.606,2.246 h1.78
  text "CN9" at -9.346,2.246 h1.78
  text "CN10" at -2.488,2.246 h1.78
  text ".GBO" at -43.387,-14.153 h3
  text ".Layer_Name" at -2.073,-14.153 h3
Top Paste:
  text ".Layer_Name" at -73.879,-14.121 h3
  text ".GTP" at -32.184,-14.121 h3
Bottom Paste:
  text ".GBP" at -43.387,-14.153 h3
  text ".Layer_Name" at -2.073,-14.153 h3
Top Solder:
  text ".Layer_Name" at -73.879,-14.121 h3
  text ".GTS" at -32.184,-14.121 h3
Bottom Solder:
  text ".GBS" at -43.387,-14.153 h3
  text ".Layer_Name" at -2.073,-14.153 h3
M1-Board Shape:
  lines w0.127: -70,4 ccw(c-68,4) -68,2 ; -70,80.5 cw(c-68,80.5) -68,82.5 ; -2,2 ccw(c-2,4) 0,4 ; -2,82.5 cw(c-2,80.5) 0,80.5
  lines w0.152: -70,4 -70,57.974 ; -70,58 -70,80.5 ; -68,2 -58.63,2 -58.5,2 -56.5,0 -23.5,0 -21.5,2 ; -68,82.5 -2,82.5 ; -21.53,2 -2,2 ; 0,4 0,57 0,80.5
M2-Board Dimensions:
  text ".Layer_Name" at -73.879,-14.121 h3
  text ".GM2" at -32.184,-14.121 h3
M16-Top Courtyard:
  lines w0.149: -46.388,10.668 ccw(c-45.888,10.668) -45.888,10.168 -41.388,10.168 -39.138,13.268 -28.638,13.268 -26.388,10.168 -21.888,10.168 ccw(c-21.888,10.668) -21.388,10.668 -21.388,15.168 -24.488,17.418 -24.488,27.918 -21.388,30.168 -21.388,34.668 ccw(c-21.888,34.668) -21.888,35.168 -26.388,35.168 -28.638,32.068 -39.138,32.068 -41.388,35.168 -45.888,35.168 ccw(c-45.888,34.668) -46.388,34.668 -46.388,30.168 -43.288,27.918 -43.288,17.418 -46.388,15.168 -46.388,10.668
Drill Drawing:
  drawing of 435 lines, arcs and shapes, not listed
  text "PCB SPECIFICATIONS :" at -69.687,124.281 h3
  text "IMPEDANCE TABLE   USB HS STLINK" at 78.921,123.918 h3
  text "A.   MATERIAL :" at -69.687,120.281 h3
  text "FR-4" at -31.187,120.281 h3
  text "TG-170" at -14.687,120.281 h3
  text "X  TG-150" at 3.563,120.281 h3
  text "TG-140" at 19.563,120.281 h3
  text "LAYER" at 83.171,118.918 h3
  text "TRACE" at 99.421,118.918 h3
  text "SPACING" at 109.921,118.918 h3
  text "IMPEDANCE" at 123.421,118.918 h3
  text "IMPEDANCE" at 140.421,118.918 h3
  text "TOL." at 159.171,118.918 h3
  text "B.   MATERIAL FAMILY :" at -69.687,117.281 h3
  text "N/A" at -31.187,117.281 h3
  text "(mm)" at 113.246,116.443 h2.5
  text "(mm)" at 101.421,116.393 h2.5
  text "(Single ended)" at 123.921,116.168 h2.5
  text "(Differential)" at 141.671,116.168 h2.5
  text "C.   SOLDERMASK COLOR :" at -69.687,114.281 h3
  text "GREEN" at -31.187,114.281 h3
  text "BLUE" at 3.563,114.281 h3
  text "BLACK" at 19.563,114.281 h3
  text "X  WHITE" at -14.553,114.26 h3
  text "+/- 15%" at 158.226,112.528 h3
  text "0.35" at 100.396,112.443 h3
  text "0.127" at 112.421,112.418 h3
  text "TOP" at 79.401,112.403 h3
  text "n/a" at 126.776,112.353 h3
  text "90 ohm" at 142.862,112.177 h3
  text "D.   SILKSCREEN COLOR :" at -69.687,111.281 h3
  text "WHITE" at -31.187,111.281 h3
  text "YELLOW" at -14.687,111.281 h3
  text "BLACK" at 3.563,111.281 h3
  text "X  Blue ink PANTONE 2955" at 19.563,111.281 h3
  text "E.   SURFACE FINISH :" at -69.687,108.281 h3
  text "X  ENIG" at -31.187,108.281 h3
  text "IMMERSION SILVER" at -14.687,108.281 h3
  text "IMMERSION TIN" at 19.563,108.281 h3
  text "HASL" at -31.187,105.281 h3
  text "HASL (PB-FREE)" at -14.687,105.281 h3
  text "GOLDEN FINGER" at 19.563,105.281 h3
  text "F.   IMPEDANCE CONTROL :" at -69.687,102.281 h3
  text "NO" at -31.187,102.281 h3
  text "X  YES  (SEE IMPEDANCE TABLE FOR DETAIL INFORMATION)" at -14.687,102.281 h3
  text "G.   THROUGH VIA :" at -69.687,99.281 h3
  text "PLUG THE VIAS WHICH ARE COVERED WITH SOLDERMASK ONE OR TWO SIDE." at -31.187,99.281 h3
  text "PLUG MATERIAL :" at -31.187,96.281 h3
  text "X  SOLDERMASK" at -5.687,96.281 h3
  text "NON-CONDUCTIVE EPOXY." at 19.563,96.281 h3
  text "PCB : TYPE 3" at 130.357,94.088 h3
  text "H.   STACK-UP :" at -69.687,93.281 h3
  text "SEE LAYER STACK-UP SEQUENCE FOR OVERALL THICKNESS." at -31.187,93.281 h3
  text "ASPECT-RATIO, AXE Z :" at 130.357,88.588 h3
  text "Layer" at 13.048,85.453 h1.52
  text "Name" at 23.459,85.453 h1.52
  text "Material" at 47.075,85.453 h1.52
  text "Thickness" at 68.913,85.453 h1.52
  text "Constant" at 85.419,85.453 h1.52
  text "Board Layer Stack" at 99.893,85.453 h1.52
  text "Top Overlay" at 23.459,82.405 h1.52
  text "6:1 to 8:1 / LEVEL \"B\"" at 130.376,81.841 h3
  text "Top Solder" at 23.459,79.357 h1.52
  text "Solder Resist" at 47.075,79.357 h1.52
  text "0.015mm" at 68.913,79.357 h1.52
  text "3.5" at 85.419,79.357 h1.52
  text "1" at 13.048,76.309 h1.52
  text "Top Layer" at 23.459,76.309 h1.52
  text "0.035mm" at 68.913,76.309 h1.52
  text "MINIMUM PARAMETERS" at 130.403,76.24 h3
  text "Dielectric 1" at 23.459,73.261 h1.52
  text "FR-4" at 47.075,73.261 h1.52
  text "1.473mm" at 68.913,73.261 h1.52
  text "4.2" at 85.419,73.261 h1.52
  text "DEFAULT" at 130.403,70.74 h3
  text "2" at 13.048,70.213 h1.52
  text "Bottom Layer" at 23.459,70.213 h1.52
  text "0.035mm" at 68.913,70.213 h1.52
  text "Bottom Solder" at 23.459,67.165 h1.52
  text "Solder Resist" at 47.075,67.165 h1.52
  text "0.015mm" at 68.913,67.165 h1.52
  text "3.5" at 85.419,67.165 h1.52
  text "TRACKS : 0.152mm           / GAPS : 0.127mm" at 130.403,64.99 h3
  text "Bottom Overlay" at 23.459,64.117 h1.52
  text "Symbol" at 13.909,54.136 h2.16
  text "Count" at 22.371,54.136 h2.16
  text "Hole Size" at 31.151,54.136 h2.16
  text "Plated" at 47.49,54.136 h2.16
  text "Hole Type" at 54.918,54.136 h2.16
  text "Drill Layer Pair" at 65.732,54.136 h2.16
  text "Via/Pad" at 86.231,54.136 h2.16
  text "Pad Shape" at 95.093,54.136 h2.16
  text "Hole Length" at 106.669,54.136 h2.16
  text "Routed Path Length" at 122.268,54.136 h2.16
  text "1" at 22.371,50.408 h1.8
  text "25.59mil (0.65mm)" at 31.151,50.408 h1.8
  text "NPTH" at 47.49,50.408 h1.8
  text "Round" at 54.918,50.408 h1.8
  text "Top Layer - Bottom Layer" at 65.732,50.408 h1.8
  text "Pad" at 86.231,50.408 h1.8
  text "Rounded" at 95.093,50.408 h1.8
  text "-" at 106.669,50.408 h1.8
  text "-" at 122.268,50.408 h1.8
  text "1" at 22.371,46.68 h1.8
  text "25.59mil (0.65mm)" at 31.151,46.68 h1.8
  text "NPTH" at 47.49,46.68 h1.8
  text "Slot" at 54.918,46.68 h1.8
  text "Top Layer - Bottom Layer" at 65.732,46.68 h1.8
  text "Pad" at 86.231,46.68 h1.8
  text "Rounded" at 95.093,46.68 h1.8
  text "37.40mil (0.95mm)" at 106.669,46.68 h1.8
  text "11.81mil (0.30mm)" at 122.268,46.68 h1.8
  text "2" at 22.371,42.951 h1.8
  text "38.19mil (0.97mm)" at 31.151,42.951 h1.8
  text "NPTH" at 47.49,42.951 h1.8
  text "Round" at 54.918,42.951 h1.8
  text "Top Layer - Bottom Layer" at 65.732,42.951 h1.8
  text "Pad" at 86.231,42.951 h1.8
  text "Rounded" at 95.093,42.951 h1.8
  text "-" at 106.669,42.951 h1.8
  text "-" at 122.268,42.951 h1.8
  text "2" at 22.371,39.223 h1.8
  text "39.37mil (1.00mm)" at 31.151,39.223 h1.8
  text "NPTH" at 47.49,39.223 h1.8
  text "Round" at 54.918,39.223 h1.8
  text "Top Layer - Bottom Layer" at 65.732,39.223 h1.8
  text "Pad" at 86.231,39.223 h1.8
  text "Rounded" at 95.093,39.223 h1.8
  text "-" at 106.669,39.223 h1.8
  text "-" at 122.268,39.223 h1.8
  text "2" at 22.371,35.495 h1.8
  text "46.85mil (1.19mm)" at 31.151,35.495 h1.8
  text "NPTH" at 47.49,35.495 h1.8
  text "Round" at 54.918,35.495 h1.8
  text "Top Layer - Bottom Layer" at 65.732,35.495 h1.8
  text "Pad" at 86.231,35.495 h1.8
  text "Rounded" at 95.093,35.495 h1.8
  text "-" at 106.669,35.495 h1.8
  text "-" at 122.268,35.495 h1.8
  text "3" at 22.371,31.767 h1.8
  text "11.81mil (0.30mm)" at 31.151,31.767 h1.8
  text "PTH" at 47.49,31.767 h1.8
  text "Round" at 54.918,31.767 h1.8
  text "Top Layer - Bottom Layer" at 65.732,31.767 h1.8
  text "Via" at 86.231,31.767 h1.8
  text "Rounded" at 95.093,31.767 h1.8
  text "-" at 106.669,31.767 h1.8
  text "-" at 122.268,31.767 h1.8
  text "3" at 22.371,28.039 h1.8
  text "125.98mil (3.20mm)" at 31.151,28.039 h1.8
  text "NPTH" at 47.49,28.039 h1.8
  text "Round" at 54.918,28.039 h1.8
  text "Top Layer - Bottom Layer" at 65.732,28.039 h1.8
  text "Pad" at 86.231,28.039 h1.8
  text "Rounded" at 95.093,28.039 h1.8
  text "-" at 106.669,28.039 h1.8
  text "-" at 122.268,28.039 h1.8
  text "4" at 22.371,24.31 h1.8
  text "19.69mil (0.50mm)" at 31.151,24.31 h1.8
  text "PTH" at 47.49,24.31 h1.8
  text "Slot" at 54.918,24.31 h1.8
  text "Top Layer - Bottom Layer" at 65.732,24.31 h1.8
  text "Pad" at 86.231,24.31 h1.8
  text "Rounded" at 95.093,24.31 h1.8
  text "43.31mil (1.10mm)" at 106.669,24.31 h1.8
  text "23.62mil (0.60mm)" at 122.268,24.31 h1.8
  text "28" at 22.371,20.582 h1.8
  text "15.75mil (0.40mm)" at 31.151,20.582 h1.8
  text "PTH" at 47.49,20.582 h1.8
  text "Round" at 54.918,20.582 h1.8
  text "Top Layer - Bottom Layer" at 65.732,20.582 h1.8
  text "Via" at 86.231,20.582 h1.8
  text "Rounded" at 95.093,20.582 h1.8
  text "-" at 106.669,20.582 h1.8
  text "-" at 122.268,20.582 h1.8
  text "32" at 22.371,16.854 h1.8
  text "43.31mil (1.10mm)" at 31.151,16.854 h1.8
  text "PTH" at 47.49,16.854 h1.8
  text "Round" at 54.918,16.854 h1.8
  text "Top Layer - Bottom Layer" at 65.732,16.854 h1.8
  text "Pad" at 86.231,16.854 h1.8
  text "Rounded" at 95.093,16.854 h1.8
  text "-" at 106.669,16.854 h1.8
  text "-" at 122.268,16.854 h1.8
  text "108" at 22.371,13.126 h1.8
  text "39.37mil (1.00mm)" at 31.151,13.126 h1.8
  text "PTH" at 47.49,13.126 h1.8
  text "Round" at 54.918,13.126 h1.8
  text "Top Layer - Bottom Layer" at 65.732,13.126 h1.8
  text "Pad" at 86.231,13.126 h1.8
  text "Rounded" at 95.093,13.126 h1.8
  text "-" at 106.669,13.126 h1.8
  text "-" at 122.268,13.126 h1.8
  text "618" at 22.371,9.397 h1.8
  text "9.84mil (0.25mm)" at 31.151,9.397 h1.8
  text "PTH" at 47.49,9.397 h1.8
  text "Round" at 54.918,9.397 h1.8
  text "Top Layer - Bottom Layer" at 65.732,9.397 h1.8
  text "Via" at 86.231,9.397 h1.8
  text "Rounded" at 95.093,9.397 h1.8
  text "-" at 106.669,9.397 h1.8
  text "-" at 122.268,9.397 h1.8
  text "804 Total" at 22.371,5.669 h1.8
  text "Slot definitions :" at 13.909,3.06 h1.8
  text "Routed Path Length" at 26.195,3.06 h1.8
  text "= Calculated from tool start centre position to tool end centre position." at 41.415,3.06 h1.8
  text "Hole Length" at 26.195,1.568 h1.8
  text "= Routed Path Length + Tool Size = Slot length as defined in the PCB layout" at 35.765,1.568 h1.8
  text ".Layer_Name" at -73.879,-14.121 h3
  text ".DRL" at -32.184,-14.121 h3
M20-Top Title Box:
  circle w0.254: c4.125,-20.842 r1.3
  region: -10.353,-21.935 -21.109,-21.935 -20.115,-19.442 -12.258,-19.442 -11.809,-18.683 -9.6,-21.231
  region: 3.651,-13.605 -11.877,-13.605 -12.571,-15.381 -13.782,-16.606 -15.179,-14.746 -15.179,-13.095 -14.036,-11.698 -12.6,-11.319 3.651,-11.319
  lines w0.254: -20.115,-19.442 -11.324,-19.442 -14.39,-15.904 cw(c-12.586,-13.96) -12.346,-11.319 4.418,-11.319 3.656,-13.605 ; -16.802,-11.072 cw(c-14.376,-12.043) -14.139,-9.44 ; -16.763,-11.04 -21.109,-21.935 -1.786,-21.935 ccw(c-1.538,-19.2) 1.012,-20.22 ; -15.023,-14.974 -9.6,-21.231 ; -14.769,-14.974 -9.464,-21.096 ; -14.769,-14.72 -9.464,-20.842 ; -14.671,-13.605 -1.678,-13.605 ; -14.642,-14.593 -9.337,-20.715 ; -14.515,-14.466 -9.21,-20.588 ; -14.388,-14.339 -9.083,-20.461 ; -14.261,-14.212 -8.956,-20.334 ; -14.206,-12.26 -8.901,-18.381 ; -14.138,-9.44 5.312,-9.44 1.013,-20.218 ; -14.134,-14.085 -8.883,-20.144 ; -14.134,-13.831 -8.829,-19.953 ; -14.134,-13.577 -8.829,-19.699 ; -14.134,-12.688 -8.829,-18.81 ; -14.007,-13.45 -8.702,-19.572 ; -14.007,-13.069 -8.702,-19.191 ; -12.635,-19.455 ccw(c-12.53,-18.92) -12.232,-18.463 ; -11.549,-13.592 ccw(c-11.574,-14.159) -11.905,-14.621 -9.54,-17.35 cw(c-11.344,-19.294) -10.611,-21.843 ; -5.267,-21.731 -2.378,-13.351 ; -5.045,-21.681 -2.176,-13.36 ; -4.918,-21.681 -2.049,-13.36 ; -4.664,-21.681 -1.795,-13.36 ; -4.41,-21.681 -1.541,-13.36 ; -4.156,-21.681 -1.287,-13.36 ; -3.902,-21.681 -1.033,-13.36 ; -3.648,-21.681 -0.779,-13.36 ; -3.394,-21.681 -0.525,-13.36 ; -3.14,-21.681 -0.271,-13.36 ; -2.931,-21.731 -0.042,-13.351 ; -0.042,-13.605 3.65,-13.605 ; 2.982,-13.603 3.744,-11.317 ; 3.148,-13.605 3.91,-11.319 ; 3.402,-13.605 4.164,-11.319
  lines w0.3: -82.879,-25.821 7.121,-25.821 7.121,-5.821 -82.879,-5.821 ; -82.879,-20.821 -22.879,-20.821 ; -82.879,-15.821 -22.879,-15.821 ; -82.879,-10.821 -22.879,-10.821 ; -82.879,-25.821 -82.879,-5.821 ; -42.879,-25.821 -42.879,-10.821 ; -22.879,-25.821 -22.879,-5.821 ; -5.267,-21.731 -2.931,-21.731
  text "Project: '.Board_Name'" at -81.879,-9.037 h3
  text "Layer:" at -81.879,-14.121 h3
  text "Gerber:" at -41.89,-14.121 h3
  text "Variant: '.VariantName'" at -81.879,-19.121 h3
  text "Ref: '.Board_Reference'" at -41.763,-19.121 h3
  text "R" at 3.617,-21.604 h1.52
  text "Date: '.Board_Document_Date'" at -81.879,-24.121 h3
  text "Rev: '.Board_PCB_Revision'" at -41.82,-24.121 h3
M21-Bottom Title Box:
  circle w0.254: c-79.696,-20.842 r1.3
  region: -79.221,-13.605 -63.694,-13.605 -63,-15.381 -61.789,-16.606 -60.392,-14.746 -60.392,-13.095 -61.535,-11.698 -62.971,-11.319 -79.221,-11.319
  region: -65.218,-21.935 -54.462,-21.935 -55.456,-19.442 -63.313,-19.442 -63.762,-18.683 -65.971,-21.231
  lines w0.254: -79.735,-11.319 -78.973,-13.605 ; -79.481,-11.319 -78.719,-13.605 ; -79.315,-11.317 -78.553,-13.603 ; -79.227,-13.605 -79.989,-11.319 -63.225,-11.319 cw(c-62.985,-13.96) -61.181,-15.904 -64.247,-19.442 -55.456,-19.442 ; -79.221,-13.605 -75.529,-13.605 ; -76.584,-20.218 -80.883,-9.44 -61.433,-9.44 ; -76.583,-20.22 ccw(c-74.033,-19.2) -73.785,-21.935 -54.462,-21.935 -58.808,-11.04 ; -75.529,-13.351 -72.64,-21.731 ; -75.3,-13.36 -72.431,-21.681 ; -75.046,-13.36 -72.177,-21.681 ; -74.792,-13.36 -71.923,-21.681 ; -74.538,-13.36 -71.669,-21.681 ; -74.284,-13.36 -71.415,-21.681 ; -74.03,-13.36 -71.161,-21.681 ; -73.893,-13.605 -60.9,-13.605 ; -73.776,-13.36 -70.907,-21.681 ; -73.522,-13.36 -70.653,-21.681 ; -73.395,-13.36 -70.526,-21.681 ; -73.193,-13.351 -70.304,-21.731 ; -66.869,-19.572 -61.564,-13.45 ; -66.869,-19.191 -61.564,-13.069 ; -66.742,-19.953 -61.437,-13.831 ; -66.742,-19.699 -61.437,-13.577 ; -66.742,-18.81 -61.437,-12.688 ; -66.688,-20.144 -61.437,-14.085 ; -66.67,-18.381 -61.365,-12.26 ; -66.615,-20.334 -61.31,-14.212 ; -66.488,-20.461 -61.183,-14.339 ; -66.361,-20.588 -61.056,-14.466 ; -66.234,-20.715 -60.929,-14.593 ; -66.107,-21.096 -60.802,-14.974 ; -66.107,-20.842 -60.802,-14.72 ; -65.971,-21.231 -60.548,-14.974 ; -64.96,-21.843 cw(c-64.227,-19.294) -66.031,-17.35 -63.666,-14.621 ccw(c-63.997,-14.159) -64.022,-13.592 ; -63.339,-18.463 ccw(c-63.041,-18.92) -62.936,-19.455 ; -61.432,-9.44 cw(c-61.195,-12.043) -58.769,-11.072
  lines w0.3: -72.64,-21.731 -70.304,-21.731 ; -52.879,-25.821 -52.879,-5.821 ; -52.879,-20.821 7.121,-20.821 ; -52.879,-15.821 7.121,-15.821 ; -52.879,-10.821 7.121,-10.821 ; -32.879,-25.821 -32.879,-10.821 ; -82.879,-25.821 -82.879,-5.821 7.121,-5.821 7.121,-25.821 -82.879,-25.821
  text "Project: '.Board_Name'" at 5.927,-9.037 h3
  text "Gerber:" at -34.062,-14.121 h3
  text "Layer:" at 5.927,-14.121 h3
  text "Ref: '.Board_Reference'" at -34.062,-19.121 h3
  text "Variant: '.VariantName'" at 5.927,-19.121 h3
  text "R" at -79.188,-21.604 h1.52
  text "Rev: '.Board_PCB_Revision'" at -34.005,-24.121 h3
  text "Date: '.Board_Document_Date'" at 5.927,-24.121 h3

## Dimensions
-10.87,22.82 to -10.87,26.884 on M2-Board Dimensions
-66.75,5.04 to -5.79,5.04 on M2-Board Dimensions
-70,80.498 to 0,80.498 on M2-Board Dimensions
-68,82.498 to -56.5,-0.002 on M2-Board Dimensions
-59.134,5.174 to -10.874,5.174 on M2-Board Dimensions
